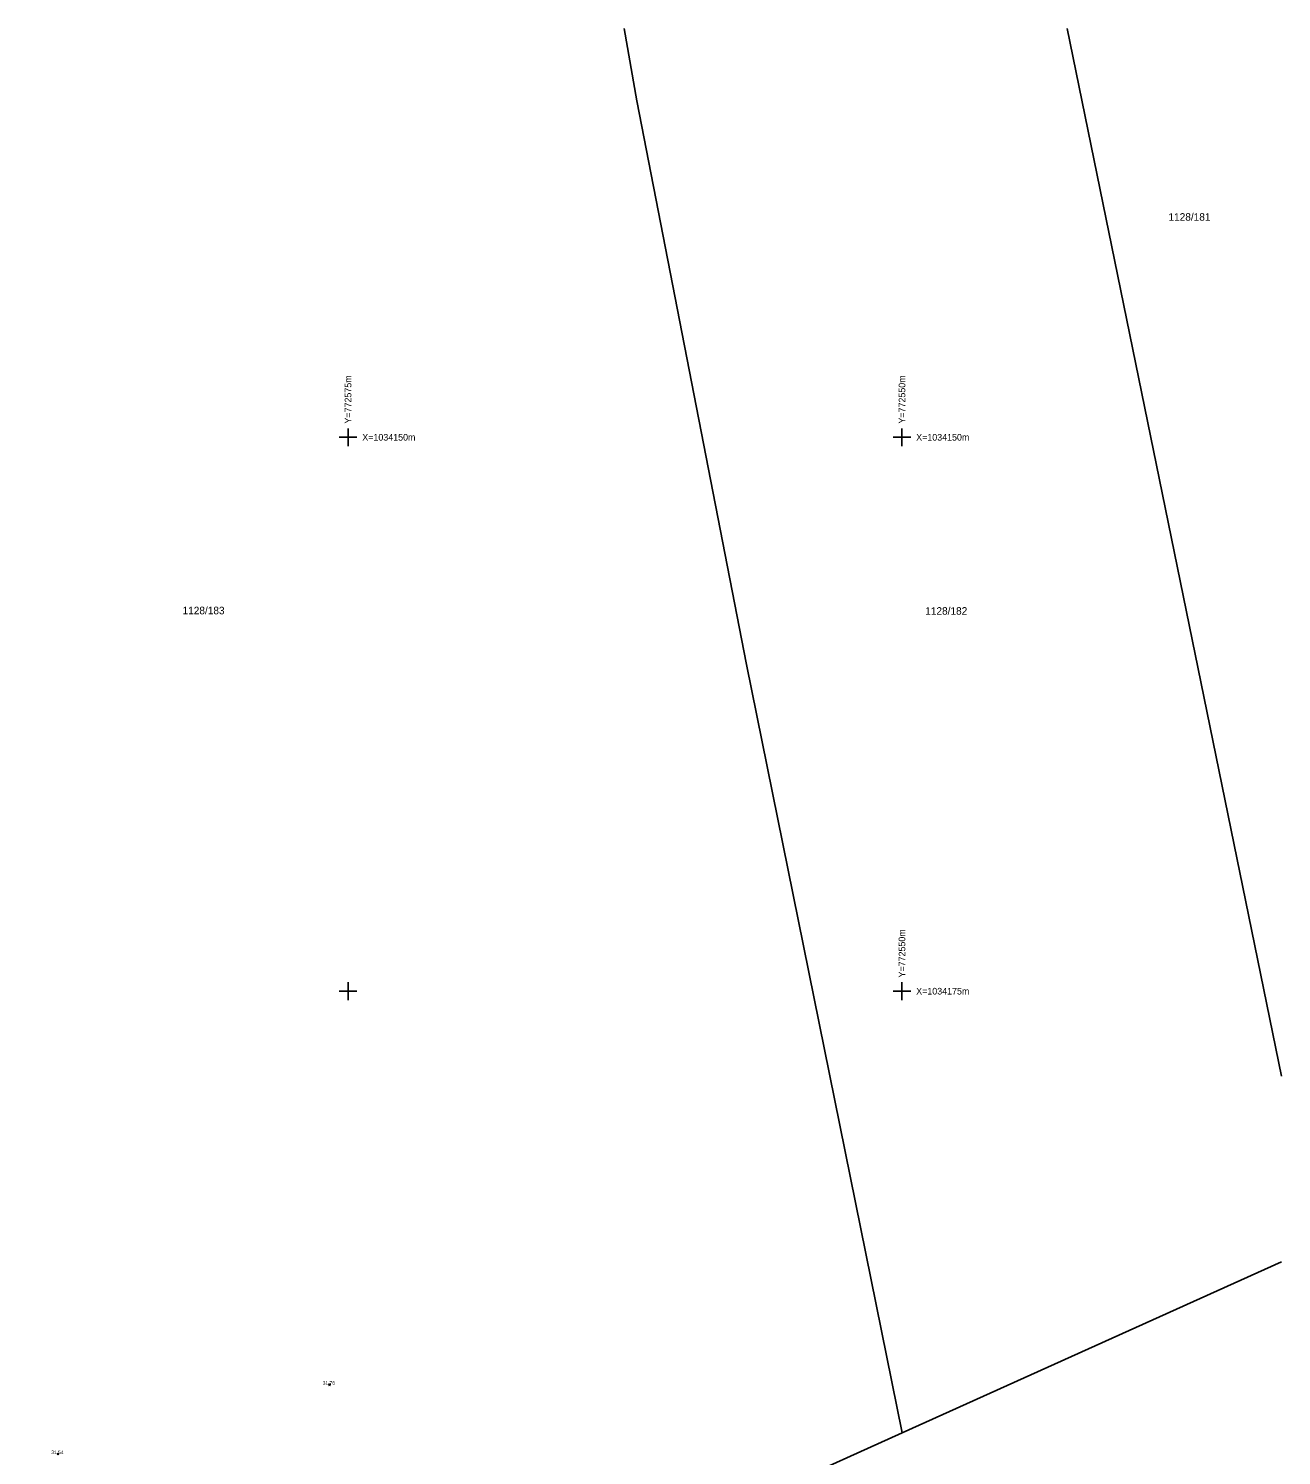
# Model space of a CAD drawing. Extents: x -772865 to -772533, y -1034366 to -1034132.
# Drawn here: x -772589.4 to -772532.9, y -1034196 to -1034131.6 of the extents above; entities that cross this region are included whole.
import ezdxf

# ---------------------------------------------------------------- set-up
doc = ezdxf.new("R2010")
doc.units = 0
for name, color, linetype in [('body', 7, 'Continuous'), ('KM_hranice', 7, 'Continuous'), ('KM_parcelni_cisla', 7, 'Continuous'), ('souradnicova_sit', 7, 'Continuous'), ('vyskove_koty', 7, 'Continuous')]:
    doc.layers.add(name, color=color, linetype=linetype)

msp = doc.modelspace()

# ---------------------------------------------------------------- linework, layer by layer
at = {"layer": 'body'}
for p, q in [((-772575.8, -1034192.8), (-772575.88, -1034192.72)), ((-772575.88, -1034192.8), (-772575.8, -1034192.72)), ((-772588.05, -1034195.93), (-772588.13, -1034195.85)), ((-772588.13, -1034195.93), (-772588.05, -1034195.85))]:
    msp.add_line(p, q, dxfattribs=at)
at = {"layer": 'KM_hranice'}
for p, q in [((-772562.546, -1034131.552), (-772561.97, -1034134.81)), ((-772542.55, -1034131.552), (-772532.872, -1034178.831)), ((-772561.97, -1034134.81), (-772557.01, -1034160.25)), ((-772557.01, -1034160.25), (-772549.99, -1034194.93)), ((-772532.872, -1034187.218), (-772549.99, -1034194.93)), ((-772549.99, -1034194.93), (-772589.6, -1034212.76))]:
    msp.add_line(p, q, dxfattribs=at)
at = {"layer": 'souradnicova_sit'}
for p, q in [((-772575.4, -1034150), (-772574.6, -1034150)), ((-772575, -1034149.6), (-772575, -1034150.4)), ((-772550.4, -1034150), (-772549.6, -1034150)), ((-772550, -1034149.6), (-772550, -1034150.4)), ((-772575.4, -1034175), (-772574.6, -1034175)), ((-772575, -1034174.6), (-772575, -1034175.4)), ((-772550.4, -1034175), (-772549.6, -1034175)), ((-772550, -1034174.6), (-772550, -1034175.4))]:
    msp.add_line(p, q, dxfattribs=at)

# ---------------------------------------------------------------- texts
at = {"layer": 'KM_parcelni_cisla'}
for s, p in [('1128/181', (-772537.972, -1034140.226)), ('1128/183', (-772582.471, -1034157.989)), ('1128/182', (-772548.95, -1034158.008))]:
    msp.add_text(s, height=0.34, dxfattribs=at).set_placement(p)
at = {"layer": 'souradnicova_sit'}
for s, p in [('Y=772575m', (-772574.85, -1034149.381)), ('Y=772550m', (-772549.85, -1034149.381)), ('Y=772550m', (-772549.85, -1034174.381))]:
    msp.add_text(s, height=0.3, rotation=90.01167, dxfattribs=at).set_placement(p)
for s, p in [('X=1034150m', (-772574.358, -1034150.15)), ('X=1034150m', (-772549.358, -1034150.15)), ('X=1034175m', (-772549.358, -1034175.15))]:
    msp.add_text(s, height=0.3, dxfattribs=at).set_placement(p)
at = {"layer": 'vyskove_koty'}
for s, p in [('31.76', (-772576.145, -1034192.76)), ('31.54', (-772588.395, -1034195.89))]:
    msp.add_text(s, height=0.16, dxfattribs=at).set_placement(p)

doc.saveas('drawing.dxf')
